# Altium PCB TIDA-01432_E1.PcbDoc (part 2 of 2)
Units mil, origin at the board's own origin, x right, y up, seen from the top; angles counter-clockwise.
Board outline 1228.35 x 2074.8 mil, 4 copper layers (Top Layer, Signal Layer 1, Signal Layer 2, Bottom Layer), stack 61.6 mil thick; 90 components, 49 nets, 292 pads, 293 vias.
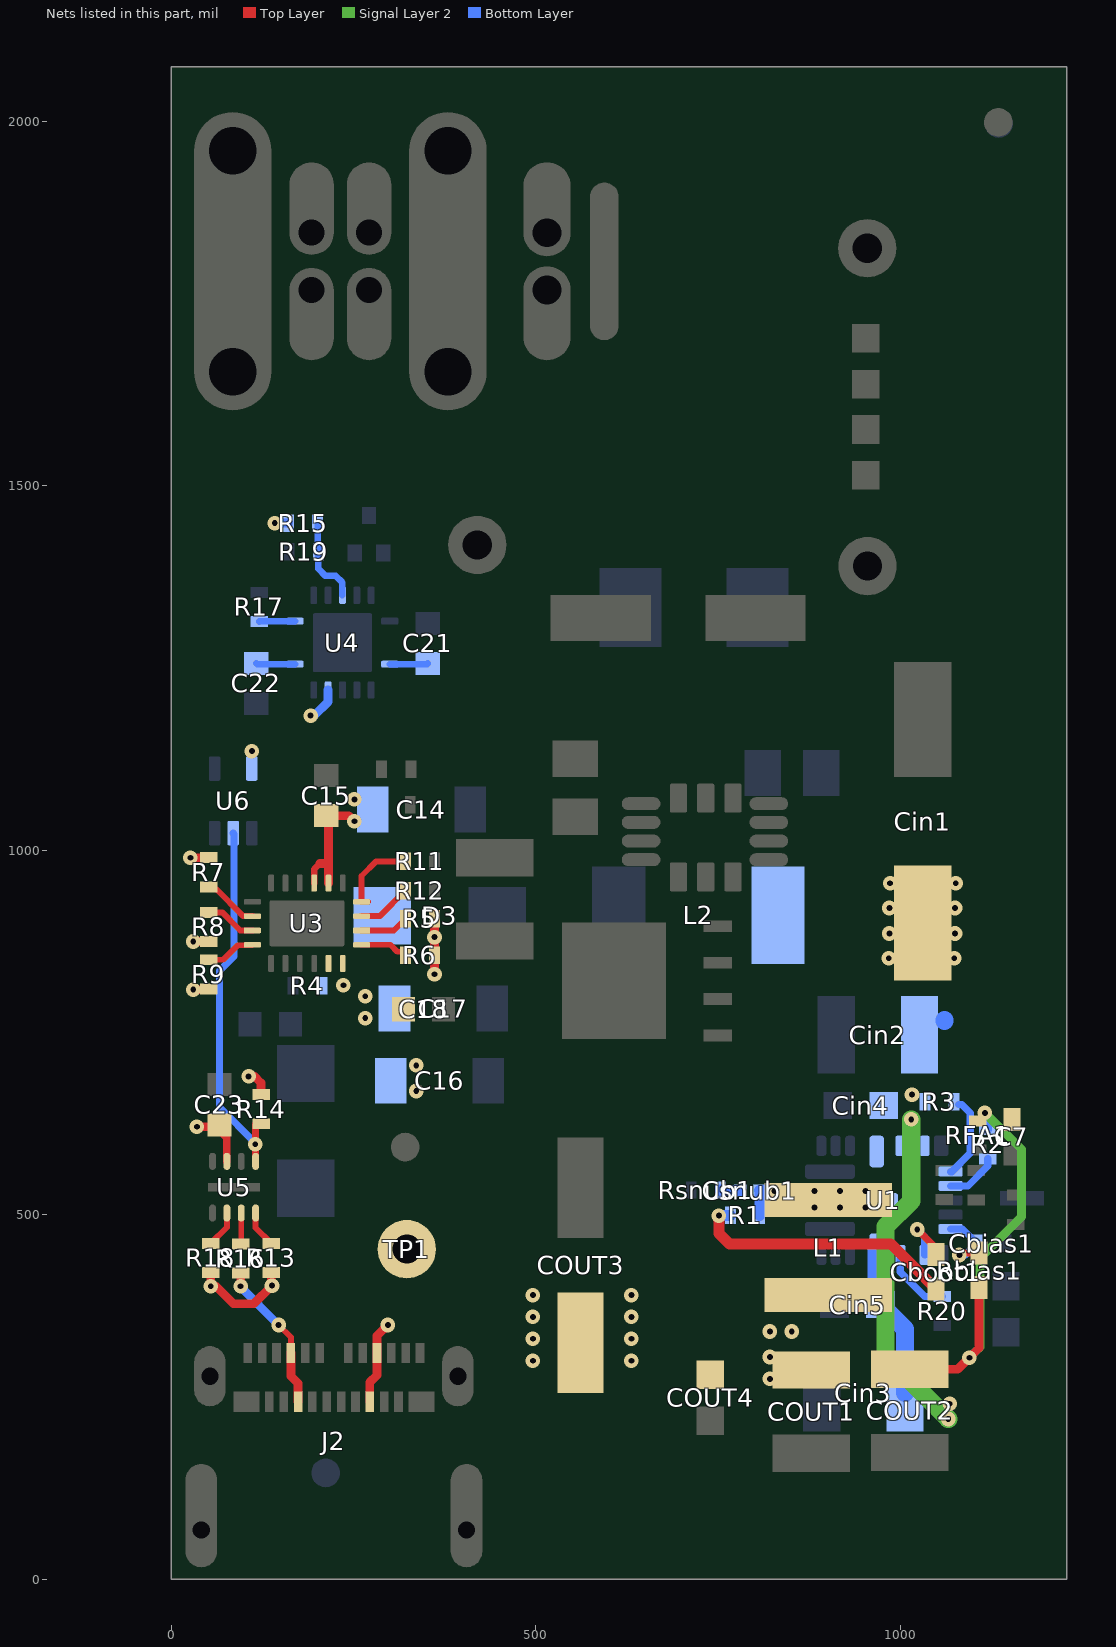
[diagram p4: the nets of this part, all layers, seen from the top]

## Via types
v1: diameter 20, hole 8, Top Layer to Bottom Layer, tented both sides, 274 vias
v2: diameter 19.68, hole 7.87, Top Layer to Bottom Layer, 12 vias
v3: diameter 16, hole 8, Top Layer to Bottom Layer, tented both sides, 7 vias

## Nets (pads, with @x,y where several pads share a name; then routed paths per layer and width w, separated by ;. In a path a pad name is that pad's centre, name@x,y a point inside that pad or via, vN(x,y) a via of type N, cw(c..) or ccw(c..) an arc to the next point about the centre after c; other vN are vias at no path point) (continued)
NetC21_1: C21.1 U4.8 | length 52.4
  Bottom Layer w9: U4.8@299.99,1255.47 351.06,1255.47 C21.1@352.03,1256.44
NetC22_1: C22.1 U4.14 | length 53.5
  Bottom Layer w9: C22.1@117.03,1256.56 118.12,1255.47 U4.14@170.07,1255.47
NetCbias1_2: Cbias1.2 Rbias1.1 U1.22 | length 103
  Top Layer w10: v1(1081.35,445) 1083.97,447.62 Rbias1.1@1108.35,447.62
  Bottom Layer w10: U1.22@1069.18,480.63 1085.72,480.63 Cbias1.2@1105.35,461 1089.35,445 v1(1081.35,445)
NetCboot1_1: Cboot1.1 R1.2 | length 369.8
  Top Layer w15: v1(751.5,499) 751.5,474.5 766,460 987.52,460 Cboot1.1@1049.15,398.38
  Bottom Layer w15: v1(751.5,499) 751.85,499.35 R1.2@767.5,499.35
NetCboot1_2: Cboot1.2 U1.2 | length 84
  Top Layer w10: v1(1023.5,480) 1049.15,454.36 Cboot1.2@1049.15,445.62
  Bottom Layer w10: v1(1023.5,480) 1033.75,469.76 U1.2@1033.75,445.2
NetCsnub1_1: Csnub1.1 Rsnub1.2 | length 27.7
  Bottom Layer w15: Rsnub1.2@753.5,534.15 754,533.65 Csnub1.1@781.01,533.65
NetR2_2: R2.2 U1.19 | length 72.4
  Bottom Layer w10: U1.19@1069.18,539.69 1093.03,539.69 1120.35,567 R2.2@1120.35,576.96
NetR3_1: R3.1 U1.18 | length 113.6
  Bottom Layer w10: U1.18@1069.18,559.37 1070.72,559.37 1096.35,585 1096.35,639.65 1084.65,651.35 R3.1@1080,651.35
NetR5_2: R5.2 U3.18 | length 66.8
  Top Layer w8: U3.18@261.15,890.16 305.5,890.16 R5.2@321.35,906
NetR6_2: R6.2 U3.17 | length 64.1
  Top Layer w8: U3.17@261.15,870.47 300.87,870.47 310.35,861 R6.2@321.35,861
NetR7_2: R7.2 U3.8 | length 65.2
  Top Layer w8: R7.2@61.78,947 98.93,909.84 U3.8@111.54,909.84
NetR8_2: R8.2 U3.9 | length 65.5
  Top Layer w8: R8.2@56.35,915 70.06,915 94.91,890.16 U3.9@111.54,890.16
NetR9_2: R9.2 U3.10 | length 68.7
  Top Layer w8: R9.2@51.35,850 71.35,850 91.35,870 111.07,870 U3.10@111.54,870.47
NetR11_2: R11.2 U3.20 | length 113
  Top Layer w8: U3.20@270.3,929.53 U3.20@261.15,929.53 261.15,964.8 281.35,985 R11.2@321.35,985
NetR12_2: R12.2 U3.19 | length 74.8
  Top Layer w8: U3.19@261.15,909.84 286.19,909.84 R12.2@321.35,945
NetR13_1: R13.1 U5.4 | length 50.5
  Top Layer w8: U5.4@115.87,502.57 115.87,482.47 R13.1@137.35,461
NetR14_1: R14.1 U5.5 U6.2 | length 506.8
  Top Layer w10: U5.5@115.87,573.43 R14.1@115.87,623.47 ; R14.1@123.35,625 R14.1@124.87,623.47
  Bottom Layer w10: U6.2@85.15,1023.71 86.35,1022.51 86.35,855 66.35,835 66.35,647.98 v1@115.87,598.45
  other v1: 115.4,596.91
NetR15_1: R15.1 R19.2 U4.4 | length 123.6
  Bottom Layer w9: R15.1@201.08,1449.04 201.08,1417.96 204.71,1414.32 202,1411.61 202,1386.39 211.76,1376.63 225.76,1376.63 235.03,1367.36 U4.4@235.03,1349.96
NetR16_2: R16.2 U5.3 | length 42.9
  Top Layer w8: R16.2@95.35,460 96.19,460.84 U5.3@96.19,502.57
NetR17_2: R17.2 U4.1 | length 49.3
  Bottom Layer w9: R17.2@121.03,1314 121.56,1314.53 U4.1@170.07,1314.53
NetR18_1: R18.1 U5.2 | length 50.7
  Top Layer w8: R18.1@54.35,461 76.5,483.16 U5.2@76.5,502.57
NetR20_1: R20.1 U1.3 | length 95.2
  Bottom Layer w10: U1.3@1000.28,445.2 1000.28,421.72 1034,388 R20.1@1058,388
P5V: C7.1 C14.1 C15.1 C23.1 COUT1.2 COUT2.2 COUT3.1 COUT4.1 L1.2 R2.1 R5.1 R6.1 R7.1 R8.1 R9.1 R13.2 R14.2 R15.2 R18.2 Rbias1.2 RFA1.2 TP1.1 U3.2 U3.3 U4.12 U5.7 U6.5 | length 1266.3
  Top Layer w9: U3.3@196.19,955.12 196.19,974.42 203.77,982 ; C15.1@212.59,1047.7 C15.1@215.87,1044.42
  Top Layer w10: C23.1@59.35,622.44 76.35,605.44 ; C23.1@76.35,611.44 76.35,605.44 ; U5.7@76.5,573.43 76.35,573.59 76.35,605.44
  Top Layer w12: v1(26.35,990) R7.1@51.35,990 ; v1(30.35,809) 50.35,809 R9.1@51.35,810 ; v1(30.35,875) R8.1@51.35,875 ; v1(35.35,621) 54.91,621 C23.1@56.35,622.44 ; R18.2@54.35,421 v1(54.35,402) 61.58,402 85.46,378.13 113.47,378.13 v1(138.35,403) 137.35,404 R13.2@137.35,421 ; C23.1@59.35,622.44 C23.1@56.35,622.44 ; C23.1@64.35,614.44 C23.1@56.35,622.44 ; v1(106.35,690) 114.35,690 123.35,681 R14.2@123.35,665 ; 203.77,982 215.87,982 ; C15.1@212.59,1047.7 243.64,1047.7 v1(251.35,1040) ; U3.2@215.87,955.12 215.87,982 ; C15.1@215.87,1044.42 215.87,982 ; v1(361.35,830) R6.1@361.35,856 R5.1@361.35,906 ; COUT2.2@1013,288.09 1079.09,288.09 1108.35,317.35 Rbias1.2@1108.35,400.38
  Signal Layer 2 w12: v1(1095,304) 1109.53,318.53 1109.53,440.53 1166.5,497.5 1166.5,589.85 v1(1116.35,640)
  Bottom Layer w12: v1(142.03,1449) 142.08,1449.04 R15.2@161.08,1449.04 ; v1(191.35,1185) 196.35,1185 215.35,1204 U4.12@215.35,1220.04 ; v1(1116.35,640) 1120.35,636 R2.1@1120.35,616.96
  other v1: 821.35,275 496.35,300 631.35,300 821.35,305 496.35,330 631.35,330 821.35,340 851.35,340 496.35,360 631.35,360 496.35,390 631.35,390 361.35,881 251.35,1070 110.74,1136.29
"SW NODE": Csnub1.2 L1.1 R1.1 U1.9 | length 51.5
  Bottom Layer w15: R1.1@807.5,499.35 807.5,533.14 Csnub1.2@806.99,533.65 v3@824,533.65
  other v3: 882.65,510 917.35,510 952.65,510 827.65,533 882.65,533 917.65,533 952.65,533
VBUS: C16.1 C17.1 C18.1 D3.2 J2.A4 J2.A9 J2.B4 J2.B9 R4.2 R16.1 U3.15 U3.16 | length 336.5
  Top Layer w8: v1(147.35,349) 164.29,332.06 J2.A4@164.29,310.6
  Top Layer w12: v1(95.35,402) R16.1@95.35,420 ; 164.29,290.98 164.29,279.06 ; J2.A4@164.29,310.6 164.29,279.06 ; J2.B9@174.13,243.67 174.13,269.21 164.29,279.06 ; J2.B4@272.56,243.67 272.56,270.21 282.35,280 282.35,288 282.4,288.06 J2.A9@282.4,310.6 282.4,334.06 v1(297.35,349)
  Bottom Layer w12: v1(95.35,402) 95.35,401 v1(147.35,349)
  other v1: 336.35,670 336.35,705 266.35,770 266.35,800 236.35,815
VIN: Cin1.1 Cin2.1 Cin3.1 Cin4.1 Cin5.1 L2.2 R3.2 U1.4 U1.14 U1.15 U1.16 | length 662.2
  Signal Layer 2 w25: v1(1015.35,631) 1015.35,519.35 980,484 980,306.15 v1(1066.15,220)
  Bottom Layer w25: U1.4@967.8,453.07 967.8,402.34 Cin5.1@978.14,392 ; Cin5.1@973.14,377 1006.73,343.41 Cin3.1@1006.73,256 ; 1060.85,766.35 1060.85,767
  other v1: 1068,241 1016.35,665 984.35,852 1074.35,852 985.35,886 1075.35,886 985.35,921 1075.35,921 986.35,955 1076.35,955
pads on no net: FID1.1 FID2.1 FID3.1 FID4.1 J1.2 J1.4 J1.@192.72,1735.78 J1.@271.46,1880.47 J2.A2 J2.A3 J2.A8 J2.A10 J2.A11 J2.B2 J2.B3 J2.B8 J2.B10 J2.B11 J2.S1 J2.S2 J2.S3 J2.S4 LBL1.0 U1.4A U1.4B U1.8A U1.8B U1.9A U1.9B U1.9C U1.9D U1.10A U1.10B U1.14A U1.14B U3.21@159.77,900 U3.21@212.92,900 U4.2 U4.3 U4.11 U4.13 U4.15@212.98,1262.95 U4.15@212.98,1307.04 U4.15@257.08,1262.95 U4.15@257.08,1307.04 U6.1 U7.3 U7.5

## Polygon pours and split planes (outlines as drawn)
GND on Signal Layer 1 "SIGNAL_LAYER_1_GND_P010" (solid, remove dead copper, pour order 10): 16.35,2060 1218.5,2060 1218.5,-62.16 1221.35,-65 6.35,-65 6.35,2056.72 9.63,2060 16.35,2060
VIN on Signal Layer 2 "SIGNAL_LAYER_2_VIN_P016" (solid, remove dead copper, pour order 16): 1085,970 961.35,970 961.35,195 1085,195
VBUS on Signal Layer 2 "SIGNAL_LAYER_2_VBUS_P018" (solid, remove dead copper, pour order 18): 311.35,300 176.35,300 141.35,335 141.35,675 161.35,695 251.35,785 356.35,785 356.35,585 241.35,470 241.35,410 241.35,400 261.35,380 266.35,375 311.35,375 311.35,295
P5V on Signal Layer 2 "SIGNAL_LAYER_2_P5V_P022" (solid, remove dead copper, pour order 22): 11.35,2064.8 1218.31,2064.8 1218.5,2065 1221.35,2062.16 1221.35,-65 11.35,-65 11.35,2064.8
GND on Top Layer "TOP_LAYER_GND_P036" (solid, remove dead copper, pour order 36): 20,2050 1210,2050 1210,20 11.19,20 11.19,2050
"INPUT POWER" on Top Layer "TOP_LAYER_INPUT_POWER_P028" (solid, remove dead copper, pour order 28): 550,1773 549,1774 481,1774 481,1503 485,1499 489,1495 825,1495 903,1495 905,1497 905,1673 555,1673 550,1678 550,1777
GND on Bottom Layer "BOTTOM_LAYER_GND_P042" (solid, remove dead copper, pour order 42): 20,2050 1210,2050 1210,20 11.19,20 11.19,2050 20,2050
"INPUT POWER" on Bottom Layer "BOTTOM_LAYER_INPUT_POWER_P040" (solid, remove dead copper, pour order 40): 470,1800 610,1800 630,1800 750,1680 1010,1680 1040,1650 1040,1250 950,1250 920,1220 740,1220 740,1390 660,1470 630,1500 470,1500 470,1800
"INPUT POWER" on Bottom Layer "BOTTOM_LAYER_INPUT_POWER_P038" (solid, remove dead copper, pour order 38): 470,1800 580,1800 580,1690 680,1710 590,1680 1000,1680 1010,1680 1040,1650 1040,1250 765.27,1250 760,1244.73 756.35,1248.39 756.35,1421.9 748.1,1421.9 610,1560 470,1560

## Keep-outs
Keep-Out Layer:
  lines w15: 1165.35,-7.5 1228.35,-7.5 ; 1197,-9.84 638.8,-8.68 -0.39,-7.5 ; -7.89,0 ccw(c-0.39,0) -0.39,-7.5 ; -7.89,0 ccw(c-0.39,0) -0.39,-7.5 ; -7.89,0 -7.89,2074.8 ; -7.89,2074.8 cw(c-0.39,2074.8) -0.39,2082.3 ; -7.89,2074.8 cw(c-0.39,2074.8) -0.39,2082.3 ; -7.5,0 ccw(c0,0) -1.47,-7.36 ; -7.5,0 ccw(c0,0) -1.47,-7.36 ; -7.5,0 -7.5,2074.8 ; -7.5,2074.8 cw(c0,2074.8) 0,2082.3 ; -7.5,2074.8 cw(c0,2074.8) 0,2082.3 ; -1.47,-7.36 ccw(c0,0) 0,-7.5 ; -1.47,-7.36 ccw(c0,0) 0,-7.5 ; -0.39,2082.3 1228.35,2082.3 ; 0,-7.5 1228.35,-7.5 ; 0,2082.3 1228.35,2082.3 ; 1228.35,-7.5 ccw(c1228.35,0) 1235.85,0 ; 1228.35,-7.5 ccw(c1228.35,0) 1235.85,0 ; 1228.35,-7.5 ccw(c1228.35,0) 1235.85,0 ; 1228.35,-7.5 ccw(c1228.35,0) 1235.85,0 ; 1228.35,2082.3 cw(c1228.35,2074.8) 1235.85,2074.8 ; 1228.35,2082.3 cw(c1228.35,2074.8) 1235.85,2074.8 ; 1228.35,2082.3 cw(c1228.35,2074.8) 1235.85,2074.8 ; 1228.35,2082.3 cw(c1228.35,2074.8) 1235.85,2074.8 ; 1235.85,0 1235.85,2074.8 ; 1235.85,0 1235.85,2074.8
  text ".Layer_Name" at 497,-923.49 h40

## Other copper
Top Layer:
  rectangle net "INPUT POWER": 484,1588 547,1710
  rectangle net "INPUT POWER": 480,1460 900,1680
  rectangle net CSPORT: 1129,546 1161,590
  rectangle net "INPUT POWER": 735,1325 1020,1501.97
  rectangle net P5V: 215.87,970 225.35,1044.42
  rectangle net VBUS: 290.35,645 343.35,824
  rectangle net CATHODE: 536.35,920 706.35,995
  rectangle net GND: 690.35,88 1080.35,173
  rectangle net P5V: 1100.35,615 1170.35,655
  rectangle net GND: 351.35,960 496.35,1080
  rectangle net CATHODE: 391.35,820 566.35,900
  rectangle net VBUS: 211.35,755 236.35,850
  rectangle net VBUS: 211.35,755 331.35,825
  rectangle net GND: 356.35,650 461.35,800
  rectangle net GND: 481.35,470 646.35,620
  rectangle net "INPUT POWER": 796.35,1060 936.35,1160
  rectangle net "INPUT POWER": 906.35,1015 936.35,1060
  rectangle net VIN: 961.35,820 1106.35,995
  rectangle net GND: 691.35,125 1031.35,235
  rectangle net GND: 521.35,1240 676.35,1430
  rectangle net "INPUT POWER": 736.35,1230 891.35,1430
  rectangle net GND: 1071.35,110 1195.47,195
  rectangle net GND: 1116.35,680 1201.35,1180
  rectangle net GND: 831.35,695 1156.35,800
  rectangle net GND: 426.35,175 766.35,235
  rectangle net "INPUT POWER": 796.35,1145 936.35,1345
  rectangle net P5V: 191.93,1035 261.35,1075
  rectangle net GND: 191.93,1095 261.35,1135
  rectangle net GND: 135.35,836 145.01,878.35
  rectangle net P5V: 480.79,270 995.61,397.8
  rectangle net "INPUT POWER": 734,1483 1019,1536
  pour cut-out: 999,491.5 997.2,489.7 754.3,489.7 777,467 999,467 999,489.5 999.5,490
  pour cut-out: 784,424.3 805.5,441.5 982.5,441.5 982.5,422.5 979,419 784,419
  text ".Layer_Name" at 497,-923.49 h70
Signal Layer 1:
  text ".Layer_Name" at 472,-921.49 h70
Signal Layer 2:
  rectangle net VIN: 1044,206 1080,253
  rectangle net VBUS: 215,730 295,828.98
  rectangle net P5V: 465.19,482.2 477.51,497.8
  text ".Layer_Name" at 451,-921.49 h70
Bottom Layer:
  rectangle net GND: 86.35,725.26 125.98,800
  rectangle net VIN: 957.65,580 1037.65,670
  rectangle net VIN: 957.65,668.91 1037.65,815.19
  rectangle net VIN: 776.35,845 1091.35,980
  rectangle net VIN: 956.35,735 1091.35,950
  rectangle net "INPUT POWER": 756.35,1235 851.35,1421.9
  rectangle net VBUS: 256.35,650 331.35,950
  rectangle net VBUS: 201.35,755 281.35,826.42
  rectangle net VBUS: 291.35,650 346.35,723.37
  rectangle net CATHODE: 571.35,840 681.35,980
  rectangle net VIN: 956.35,213.3 1031.35,363.3
  rectangle net VIN: 1016.58,205 1071.72,250
  rectangle net P5V: 811.35,265 851.35,350
  rectangle net VIN: 956.35,200 1031.35,213.3
  text ".Layer_Name" at 497,-923.49 h60

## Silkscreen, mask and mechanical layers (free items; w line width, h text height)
Top Overlay:
  circle w10: c819,956 r7.81
  circle w10: c770,1128 r9.34
  region: 1084,33 1084,110 901,110 901,33
  lines w3.94: 341.35,1010 434.35,1103 434.35,1122
  lines w6: 645,1080.95 645,1113 ; 723,1104 723,1130
  text "GND" at 910.27,1901.63 h40
  text "GND" at 390.27,1321.66 h40
  text "INPUT POWER" at 906,1291 h40
  text "5V" at 304.27,518.66 h40
  text "TIDA-01432-" at 460,62 h40
  text ".Layer_Name" at 497,-923.49 h40
Bottom Overlay:
  text ".Layer_Name" at 497,-923.49 h40
Top Paste:
  text ".Layer_Name" at 497,-923.49 h40
Bottom Paste:
  text ".Layer_Name" at 497,-923.49 h40
Top Solder:
  text ".Layer_Name" at 497,-923.49 h40
Bottom Solder:
  text ".Layer_Name" at 497,-923.49 h40
Drill Guide:
  text ".Layer_Name" at 497,-923.49 h40
M1 Board Outline:
  the board outline again, w3.94
  text ".Layer_Name" at 497,-923.49 h60
M2 Board Dimensions:
  rectangle: 45,-465 420,-340
  rectangle: -80,-340 45,-215
  lines w7: -80,-340 920,-340 ; -80,-215 -80,-465 920,-465 920,-215 ; 45,-465 45,-215 ; 170,-465 170,-215 ; 420,-465 420,-215 ; 670,-465 670,-215
  text ".Layer_Name" at 497,-923.49 h60
M3 3D STEP Top:
  text ".Layer_Name" at 497,-923.49 h40
M4 3D STEP Bottom:
  text ".Layer_Name" at 497,-923.49 h40
M5 Assembly Top:
  lines w10: -372,-995.17 6228,-995.17 ; -372,-791.83 6230,-791.83 ; -372,-588.5 -372,-1198.5 3633,-1198.5 6230,-1198.5 6230,-588.5 -371.5,-588.5 -371.5,-1198.5 1204,-1198.5 ; 2093,-1198.5 2093,-588.5 ; 3360,-791.83 3360,-588.5 ; 4200,-791.83 4200,-588.5 ; 4822,-1205 4822,-1002.17
  text "COMPONENTS MARKED 'DNP' SHOULD NOT BE POPULATED." at 1073.5,-383.5 h60
  text "ASSEMBLY VARIANT:" at 1073,-499 h60
  text ".VariantName" at 2109,-499 h60
  text "PCB VIEWED FROM TOP SIDE" at -308.5,-720.67 h60
  text "BOARD #:" at 2168,-720.67 h40
  text ".PRJ_Number" at 2713.5,-720.67 h40
  text "REV:" at 3558,-720.67 h40
  text ".PCB_Rev" at 3849.5,-720.67 h40
  text "SVN REV:" at 4396,-720.67 h40
  text ".VersionControl_RevNumber" at 4902,-720.67 h40
  text "TID #:" at 2168,-924 h40
  text ".TID" at 2713.5,-924 h40
  text ".Layer_Name" at 492.47,-930.49 h70
  text "PLOT NAME =" at -308.5,-1129.34 h60
  text ".plot_File_Name" at 497,-1129.34 h40
  text "GENERATED    :" at 2170,-1129.34 h40
  text ".Print_Date" at 3039.5,-1129.34 h40
  text ".Print_Time" at 3768.5,-1129.34 h40
  text "TEXAS INSTRUMENTS" at 5033,-1129.34 h40
M6 Assembly Bottom:
  lines w10: -372.5,-792.33 6229.5,-792.33 ; -370.5,-995.67 6229.5,-995.67 ; 1035.5,-1205.5 1035.5,-1002.67 ; 1657.5,-792.33 1657.5,-589 ; 2497.5,-792.33 2497.5,-589 ; 3764.5,-1199 3764.5,-589 ; 4653.5,-1199 6229,-1199 6229,-589 -372.5,-589 -372.5,-1199 2224.5,-1199 6229.5,-1199 6229.5,-589
  text "COMPONENTS MARKED 'DNP' SHOULD NOT BE POPULATED." at 6022,-383 h40
  text ".VariantName" at 4978,-499 h40
  text "ASSEMBLY VARIANT:" at 6017,-499 h40
  text ".VersionControl_RevNumber" at 955.5,-721.17 h40
  text "SVN REV:" at 1461.5,-721.17 h40
  text ".PCB_Rev" at 2008,-721.17 h40
  text "REV:" at 2299.5,-721.17 h40
  text ".PRJ_Number" at 3144,-721.17 h40
  text "BOARD #:" at 3689.5,-721.17 h40
  text "PCB VIEWED FROM BOTTOM SIDE" at 6166,-721.17 h40
  text ".TID" at 3144,-924.5 h40
  text "TID #:" at 3689.5,-924.5 h40
  text "TEXAS INSTRUMENTS" at 824.5,-1129.84 h40
  text ".Print_Time" at 2089,-1129.84 h40
  text ".Print_Date" at 2818,-1129.84 h40
  text "GENERATED    :" at 3687.5,-1129.84 h40
  text ".plot_File_Name" at 5360.5,-1129.84 h40
  text "PLOT NAME =" at 6166,-1129.84 h40
M9 Title Sheet:
  drawing of 57 lines, arcs and shapes, not listed
  text "1" at 659.84,7971.5 h40
  text "2" at 3155.5,7971.5 h40
  text "3" at 5644.84,7971.5 h40
  text "4" at 8151.51,7971.5 h40
  text "5" at 10650.5,7971.5 h40
  text "6" at 13155.5,7971.5 h40
  text "A" at -496.5,6828.5 h70
  text "A" at 14303.5,6828.5 h70
  text "B" at -496.5,4448.5 h70
  text "B" at 14303.5,4448.5 h70
  text "C" at -496.5,2073.5 h70
  text "C" at 14303.5,2073.5 h70
  text "PROJECT TITLE:" at 11263.5,212.5 h40
  text ".PRJ_Title" at 11313.5,79.17 h70
  text "DESIGNED FOR:" at 11263.5,-88.5 h40
  text ".PRJ_Customer" at 11313.5,-228.5 h70
  text "D" at -496.5,-296.5 h70
  text "D" at 14303.5,-296.5 h70
  text "FILE NAME:" at 11263.5,-388.5 h40
  text ".PCB_File_Name_No_Path" at 11313.5,-508.5 h70
  text "Texas Instruments (TI) and/or its licensors do not warrant the accuracy or completeness of this specification" at 6302,-677.34 h45
  text "ENGINEER:" at 11263.5,-678.5 h40
  text "LAYOUT BY:" at 12768.5,-678.5 h40
  text "or any information contained therein. TI and/or its licensors do not warrant that this design will meet" at 6257.01,-790 h45
  text ".PRJ_Engineer" at 11313.5,-833.49 h70
  text ".PCB_Layout" at 12819,-833.49 h70
  text "the specifications, will be suitable for your application or fit for any particular purpose, or will operate in" at 6257.01,-902.67 h45
  text ".Layer_Name" at 497,-923.49 h40
  text "ALTIUM DESIGNER VERSION:" at 12768.5,-988.5 h40
  text "an implementation. TI and/or its licensors do not warrant that the design is production worthy. You should" at 6257.01,-1015.33 h45
  text ".print_Scale" at 11313.5,-1121.83 h70
  text ".Application_BuildNumber" at 12819,-1121.83 h70
  text "completely validate and test your design implementation to confirm the system functionality for your application." at 6302,-1128 h45
  text "1" at 659.84,-1328.5 h40
  text "2" at 3155.5,-1328.5 h40
  text "3" at 5644.84,-1328.5 h40
  text "4" at 8151.51,-1328.5 h40
  text "5" at 10650.5,-1328.5 h40
  text "6" at 13155.5,-1328.5 h40
M10 Fab Notes:
  drawing of 173 lines, arcs and shapes, not listed
  text "DESIGN INFORMATION" at 12298.02,6136 h60
  text "MIN. TRACK WIDTH:" at 11653.46,5956 h61
  text "8" at 12749.7,5956 h60
  text "MIL" at 12904.46,5956 h60
  text "8" at 12749.7,5834 h60
  text "MIN. CLEARANCE:" at 11653.46,5824 h61
  text "MIL" at 12904.46,5824 h60
  text "MIN. VIA PAD SIZE:" at 11653.46,5692 h60
  text "16" at 12719.71,5692 h60
  text "MIL" at 12904.46,5692 h60
  text "0.05mm (2MIL)" at 12348.46,5550.29 h60
  text "MINIMUM ANNULAR RING" at 11324.23,5546 h60
  text "EXTERNAL" at 13056.46,5546 h60
  text "PER" at 11524.23,5428 h60
  text "IPC-D-275 CLASS 2 LEVEL C" at 11744.23,5428 h60
  text "MIL, HOLES" at 13232.46,5315.71 h60
  text "+/-" at 12840,5315 h60
  text "+/-" at 13694,5315 h60
  text "REGISTRATION TOLERANCES:" at 11324.23,5310 h60
  text "METAL" at 12524,5310 h60
  text "5" at 13100.2,5310 h60
  text "3" at 13933.2,5310 h60
  text "MIL" at 14049.46,5310 h60
  text "+/-" at 13694,5197 h60
  text "HOLE SIZE TOLERANCE (UNLESS OTHERWISE SPECIFIED):" at 11324.23,5192 h60
  text "3" at 13933.2,5192 h60
  text "MIL" at 14049.46,5192 h60
  text "MATERIAL:" at 11249.46,4982.54 h60
  text "FR-4 High Tg" at 12235.9,4842.21 h60
  text "FR-408" at 11670.46,4833.64 h60
  text "OTHER" at 13158.46,4833.64 h60
  text "X" at 12081,4830 h60
  text "62 MIL (1.6mm) +/-10%" at 11990.56,4670.92 h60
  text "THICKNESS:" at 11324.23,4666.64 h60
  text "X" at 11862.4,4666.64 h60
  text "OTHER" at 13275.46,4666.64 h60
  text "TOLERANCE:" at 11324.23,4508.64 h60
  text "X" at 12163.53,4508.64 h60
  text "ANSI IPC-6012 TYPE 3 CLASS 2" at 12350.48,4508.64 h60
  text "OTHER +/-" at 12350.46,4352.64 h60
  text "BOW & TWIST:" at 11324.23,4195.64 h60
  text "X" at 12163.53,4195.64 h60
  text "ANSI IPC-6012 TYPE 3 CLASS 2" at 12350.48,4195.64 h60
  text "OTHER +/-" at 12350.46,4037.13 h60
  text "DRILLING:" at 11249.46,3898.64 h60
  text "REFERENCE:" at 11324.23,3781.64 h60
  text "X" at 11972.46,3781.64 h60
  text "AS SHOWN" at 12159.46,3781.64 h60
  text "X" at 12873.46,3781.64 h60
  text "NC_DRILL FILES" at 13010.46,3781.64 h60
  text "PTH COPPER THICKNESS:" at 11324.23,3623.64 h60
  text "X" at 12454.46,3623.64 h60
  text "20-30 um" at 12591.46,3623.64 h60
  text "OTHER" at 13308.46,3623.64 h60
  text "BOARD FINISH:" at 11249.46,3464.64 h60
  text "SILKSCREEN:" at 11404.68,3346.64 h60
  text "X" at 12353.46,3346.64 h60
  text "TOP" at 12479.46,3346.64 h60
  text "X" at 12863.46,3346.64 h60
  text "BOTTOM" at 12990.46,3346.64 h60
  text "SILKSCREEN COLOR:" at 11404.68,3179.64 h60
  text "X" at 12352.42,3179.64 h60
  text "WHITE" at 12479.46,3179.64 h60
  text "OTHER" at 12990.46,3179.64 h60
  text "X" at 12483.42,3020.44 h60
  text "GREEN" at 12610.46,3020.44 h60
  text "OTHER" at 13228.46,3020.44 h60
  text "SOLDER RESIST COLOR:" at 11404.68,3009.64 h60
  text "X" at 12483.42,2850.44 h60
  text "MATTE" at 12610.46,2850.44 h60
  text "SEMI-GLOSS" at 13228,2849.8 h60
  text "IMMERSION GOLD (ENIG)" at 12310.46,2661.92 h60
  text "ENEPIG" at 13648,2658.64 h60
  text "SURFACE FINISH:" at 11249.46,2657.64 h60
  text "X" at 12123.51,2657.64 h60
  text "IMM. TIN/SILVER OR EQUIV" at 11579,2500.64 h60
  text "OTHER" at 13010.46,2500.64 h60
  text "ARRAY/PANEL:" at 11249.46,2321.64 h60
  text "CUT AND TRIM PER M1 BOARD OUTLINE" at 12310.46,2317.35 h60
  text "N.C. ROUTE" at 12310.46,2165.64 h60
  text "V. SCORE" at 13176.46,2165.64 h60
  text "X" at 12099.46,2155.64 h60
  text "CERTIFICATION:" at 11249.46,2028.64 h60
  text "MATERIALS AND WORKMANSHIP FOR ALL PCBS" at 11974.46,2028.64 h60
  text "TO MEET OR EXCEED THE REQUIREMENTS OF:" at 11974.46,1930.64 h60
  text "X" at 11600.96,1794.13 h60
  text "ANSI IPC-A-600F CLASS ->" at 11739.96,1794.13 h60
  text "X" at 13379.02,1794.13 h60
  text "2" at 13497.96,1794.14 h60
  text "1" at 13182.96,1792.64 h60
  text "3" at 13851.96,1792.64 h60
  text "X" at 12415.02,1634.64 h60
  text "RoHS" at 12551.96,1634.64 h60
  text "OTHER" at 13196.36,1634.64 h60
  text "PER ORDER" at 13593.42,1634.64 h60
  text "ALL BOARDS MUST MEET OR EXCEED UL94-V0 REQUIREMENTS." at 11277,1469 h60
  text "PCB MUST BEAR THE UL94V-0 UL REGISTERED MATERIAL ID NUMBER" at 11277,1349 h60
  text "ADDITIONAL REQUIREMENTS:" at 11249.46,1175.64 h60
  text "MICROSECTION:" at 11324.23,1060.64 h60
  text "YES" at 12229.96,1060.64 h60
  text "REQUIRED" at 13091.46,904.49 h60
  text "BARE BOARD ELEC. TEST:" at 11324.23,901.64 h60
  text "NONE" at 12629.96,901.64 h60
  text "X" at 12964.46,901.64 h60
  text "PER ORDER" at 13683.46,901.64 h60
  text ".Layer_Name" at 497,-923.49 h60
M11 Gerber Information:
  lines w10: -372,-995.17 6228,-995.17 ; -372,-791.83 6230,-791.83 ; -372,-588.5 -372,-1198.5 3633,-1198.5 6230,-1198.5 6230,-588.5 -371.5,-588.5 -371.5,-1198.5 1204,-1198.5 ; 2093,-1198.5 2093,-588.5 ; 3360,-791.83 3360,-588.5 ; 4200,-791.83 4200,-588.5 ; 4822,-1205 4822,-1002.17
  text "ALL ARTWORK VIEWED FROM TOP SIDE" at -308.5,-720.67 h40
  text "BOARD #:" at 2168,-720.67 h40
  text ".PRJ_Number" at 2713.5,-720.67 h40
  text "REV:" at 3558,-720.67 h40
  text ".PCB_Rev" at 3849.5,-720.67 h40
  text "SVN REV:" at 4396,-720.67 h40
  text ".VersionControl_RevNumber" at 4902,-720.67 h40
  text "LAYER NAME =" at -308.5,-923.49 h40
  text "TID #:" at 2168,-924 h40
  text ".TID" at 2713.5,-924 h40
  text "PLOT NAME =" at -308.5,-1129.34 h40
  text ".plot_File_Name" at 497,-1129.34 h40
  text "GENERATED    :" at 2170,-1129.34 h40
  text ".Print_Date" at 3039.5,-1129.34 h40
  text ".Print_Time" at 3768.5,-1129.34 h40
  text "TEXAS INSTRUMENTS" at 5033,-1129.34 h40
M12 Stackup:
  drawing of 295 lines, arcs and shapes, not listed
  text "Layer" at 10124.84,7815 h40
  text "Name" at 10404.79,7815 h40
  text "Material" at 11037.95,7815 h40
  text "Thickness" at 11617.79,7815 h40
  text "Constant" at 12057.68,7815 h40
  text "Board Layer Stack" at 12444.26,7815 h40
  text "1" at 10124.84,7735 h40
  text "Top Overlay" at 10404.79,7735 h40
  text "2" at 10124.84,7655 h40
  text "Top Solder" at 10404.79,7655 h40
  text "Solder Resist" at 11037.95,7655 h40
  text "0.40mil" at 11617.79,7655 h40
  text "3.5" at 12057.68,7655 h40
  text "3" at 10124.84,7575 h40
  text "Top Layer" at 10404.79,7575 h40
  text "Copper" at 11037.95,7575 h40
  text "1.40mil" at 11617.79,7575 h40
  text "4" at 10124.84,7495 h40
  text "Dielectric1" at 10404.79,7495 h40
  text "FR-4" at 11037.95,7495 h40
  text "6.00mil" at 11617.79,7495 h40
  text "4.8" at 12057.68,7495 h40
  text "5" at 10124.84,7415 h40
  text "Signal Layer 1" at 10404.79,7415 h40
  text "Copper" at 11037.95,7415 h40
  text "1.40mil" at 11617.79,7415 h40
  text "6" at 10124.84,7335 h40
  text "Dielectric2" at 10404.79,7335 h40
  text "44.00mil" at 11617.79,7335 h40
  text "4.2" at 12057.68,7335 h40
  text "7" at 10124.84,7255 h40
  text "Signal Layer 2" at 10404.79,7255 h40
  text "Copper" at 11037.95,7255 h40
  text "1.40mil" at 11617.79,7255 h40
  text "8" at 10124.84,7175 h40
  text "Dielectric 3" at 10404.79,7175 h40
  text "6.00mil" at 11617.79,7175 h40
  text "4.2" at 12057.68,7175 h40
  text "9" at 10124.84,7095 h40
  text "Bottom Layer" at 10404.79,7095 h40
  text "Copper" at 11037.95,7095 h40
  text "1.40mil" at 11617.79,7095 h40
  text "10" at 10124.84,7015 h40
  text "Bottom Solder" at 10404.79,7015 h40
  text "Solder Resist" at 11037.95,7015 h40
  text "0.40mil" at 11617.79,7015 h40
  text "3.5" at 12057.68,7015 h40
  text "11" at 10124.84,6935 h40
  text "Bottom Overlay" at 10404.79,6935 h40
  text ".Layer_Name" at 497,-923.49 h40
M13 Component Bodies Top:
  text ".Layer_Name" at 497,-923.49 h40
M14 Component Bodies Bottom:
  text ".Layer_Name" at 497,-923.49 h40
M15 Courtyards Top:
  text ".Layer_Name" at 497,-923.49 h40
M16 Courtyards Bottom:
  text ".Layer_Name" at 497,-923.49 h40
Drill Drawing:
  circle w10: c1647.3,2085.18 r16.59
  circle w10: c1647.3,2085.18 r27.66
  lines w10: 1619.64,1186.31 1619.64,1200.14 1633.47,1213.97 1619.64,1227.79 1619.64,1241.62 1633.47,1241.62 1647.3,1227.79 1661.13,1241.62 1674.96,1241.62 1674.96,1227.79 1661.13,1213.97 1674.96,1200.14 1674.96,1186.31 1661.13,1186.31 1647.3,1200.14 1633.47,1186.31 1619.64,1186.31 ; 1619.64,1338.42 1647.3,1310.77 1674.96,1338.42 1647.3,1366.08 1619.64,1338.42 ; 1619.64,1449.05 1633.47,1449.05 1647.3,1435.23 1661.13,1449.05 1674.96,1449.05 1661.13,1462.88 1674.96,1476.71 1661.13,1476.71 1647.3,1490.54 1633.47,1476.71 1619.64,1476.71 1633.47,1462.88 1619.64,1449.05 ; 1619.64,1559.68 1674.96,1559.68 1674.96,1615 1619.64,1615 1619.64,1559.68 ; 1619.64,1739.46 1674.96,1739.46 1647.3,1684.14 1619.64,1739.46 ; 1619.64,1808.6 1647.3,1822.43 1674.96,1808.6 1661.13,1836.26 1674.96,1863.92 1647.3,1850.09 1619.64,1863.92 1633.47,1836.26 1619.64,1808.6 ; 1619.64,1988.38 1674.96,1988.38 1647.3,1933.06 1619.64,1988.38 ; 1630.71,1977.31 1663.89,1977.31 1647.3,1944.12 1630.71,1977.31
  lines w12: 1569.5,1148.97 5364.01,1148.97 ; 1569.5,2144.64 5364.01,2144.64 ; 1907.67,1024.51 1907.67,2269.1 ; 2239.78,1024.51 2239.78,2269.1 ; 2876.79,1024.51 2876.79,2269.1 ; 3136.14,1024.51 3136.14,2269.1 ; 3511.56,1024.51 3511.56,2269.1 ; 4235.41,1024.51 4235.41,2269.1 ; 4764.92,1024.51 4764.92,2269.1 ; 1569.5,1024.51 5364.01,1024.51 5364.01,2269.1 1569.5,2269.1 1569.5,1024.51
  text "Symbol" at 1644.18,2181.98 h72
  text "Quantity" at 1945.01,2181.98 h72
  text "Finished Hole Size" at 2277.12,2181.98 h72
  text "Plated" at 2914.12,2181.98 h72
  text "Hole Type" at 3173.48,2181.98 h72
  text "Drill Layer Pair" at 3548.9,2181.98 h72
  text "Hole Tolerance" at 4272.75,2181.98 h72
  text "Hole Length" at 4802.26,2181.98 h72
  text "12" at 1945.01,2057.52 h60
  text "7.87mil (0.200mm)" at 2277.12,2057.52 h60
  text "PTH" at 2914.12,2057.52 h60
  text "Round" at 3173.48,2057.52 h60
  text "Top Layer - Bottom Layer" at 3548.9,2057.52 h60
  text "-" at 4802.26,2057.52 h60
  text "281" at 1945.01,1933.06 h60
  text "8.00mil (0.203mm)" at 2277.12,1933.06 h60
  text "PTH" at 2914.12,1933.06 h60
  text "Round" at 3173.48,1933.06 h60
  text "Top Layer - Bottom Layer" at 3548.9,1933.06 h60
  text "-" at 4802.26,1933.06 h60
  text "4" at 1945.01,1808.6 h60
  text "35.43mil (0.900mm)" at 2277.12,1808.6 h60
  text "PTH" at 2914.12,1808.6 h60
  text "Round" at 3173.48,1808.6 h60
  text "Top Layer - Bottom Layer" at 3548.9,1808.6 h60
  text "+3.94mil" at 4272.75,1808.6 h60
  text "-" at 4802.26,1808.6 h60
  text "2" at 1945.01,1684.14 h60
  text "39.37mil (1.000mm)" at 2277.12,1684.14 h60
  text "PTH" at 2914.12,1684.14 h60
  text "Round" at 3173.48,1684.14 h60
  text "Top Layer - Bottom Layer" at 3548.9,1684.14 h60
  text "+3.94mil" at 4272.75,1684.14 h60
  text "-" at 4802.26,1684.14 h60
  text "4" at 1945.01,1559.68 h60
  text "40.00mil (1.016mm)" at 2277.12,1559.68 h60
  text "PTH" at 2914.12,1559.68 h60
  text "Round" at 3173.48,1559.68 h60
  text "Top Layer - Bottom Layer" at 3548.9,1559.68 h60
  text "-" at 4802.26,1559.68 h60
  text "4" at 1945.01,1435.23 h60
  text "64.96mil (1.650mm)" at 2277.12,1435.23 h60
  text "PTH" at 2914.12,1435.23 h60
  text "Round" at 3173.48,1435.23 h60
  text "Top Layer - Bottom Layer" at 3548.9,1435.23 h60
  text "+3.94mil" at 4272.75,1435.23 h60
  text "-" at 4802.26,1435.23 h60
  text "2" at 1945.01,1310.77 h60
  text "23.62mil (0.600mm)" at 2277.12,1310.77 h60
  text "PTH" at 2914.12,1310.77 h60
  text "Slot" at 3173.48,1310.77 h60
  text "Top Layer - Bottom Layer" at 3548.9,1310.77 h60
  text "+/-1.97mil" at 4272.75,1310.77 h60
  text "62.99mil (1.600mm)" at 4802.26,1310.77 h60
  text "2" at 1945.01,1186.31 h60
  text "23.62mil (0.600mm)" at 2277.12,1186.31 h60
  text "PTH" at 2914.12,1186.31 h60
  text "Slot" at 3173.48,1186.31 h60
  text "Top Layer - Bottom Layer" at 3548.9,1186.31 h60
  text "+/-1.97mil" at 4272.75,1186.31 h60
  text "82.68mil (2.100mm)" at 4802.26,1186.31 h60
  text "311 Total" at 1945.01,1061.85 h60
  text "Slot definitions :" at 1644.18,974.73 h60
  text "Routed Path Length" at 2094.58,974.73 h60
  text "= Calculated from tool start centre position to tool end centre position." at 2633.79,974.73 h60
  text "Hole Length" at 2094.58,924.95 h60
  text "= Routed Path Length + Tool Size = Slot length as defined in the PCB layout" at 2434.19,924.95 h60
  text ".Layer_Name" at 497,-923.49 h60
M17 Embedded Cavity:
  text ".Layer_Name" at 497,-923.49 h40
M18 Embedded Assembly:
  text ".Layer_Name" at 497,-923.49 h40
M19 Embedded Keepout:
  text ".Layer_Name" at 497,-923.49 h40
Mechanical 20:
  lines w0.05: 557.79,-10 1.35,-10 ; 557.79,9.68 1.35,9.68 -3.57,8.37 -7.18,4.76 -8.5,-0.16 ; 664.64,2.84 1129.2,2.84 ; 1155.05,8.01 1160.82,9.26 1166.7,9.68 ; 1155.88,-12.91 1161.1,-10.74 1166.7,-10 ; 1158.18,-5.08 1161.78,-8.68 1166.7,-10 ; 1158.18,4.76 1161.78,8.37 1166.7,9.68 ; -8.5,-0.16 -7.18,-5.08 ; -8.5,-0.16 -7.18,-5.08 ; -8.5,-0.16 -8.5,2074.65 ; -8.5,2074.65 -7.18,2079.57 ; -8.5,2074.65 -7.18,2069.72 -3.57,2066.12 1.35,2064.8 1229.69,2064.8 1234.61,2066.12 1238.22,2069.72 1239.54,2074.65 ; -8.5,2074.65 -7.18,2079.57 ; -7.18,-5.08 -3.57,-8.68 ; -7.18,-5.08 -3.57,-8.68 ; -7.18,2079.57 -3.57,2083.17 ; -7.18,2079.57 -3.57,2083.17 ; -3.57,-8.68 1.35,-10 ; -3.57,-8.68 1.35,-10 ; -3.57,2083.17 1.35,2084.49 ; -3.57,2083.17 1.35,2084.49 ; 1.35,-10 6.27,-8.68 9.87,-5.08 11.19,-0.16 11.19,2074.65 9.87,2079.57 6.27,2083.17 1.35,2084.49 ; 1.35,2084.49 1229.69,2084.49 ; 1166.7,-10 1229.69,-10 ; 1166.7,-10 1171.63,-8.68 1175.22,-5.08 1176.54,-0.16 1175.22,4.76 1171.62,8.37 1166.7,9.68 ; 1166.7,9.68 1229.69,9.68 1234.61,8.37 1238.22,4.76 1239.54,-0.16 ; 1166.7,9.68 1166.7,9.68 ; 1229.69,-10 1234.61,-8.68 ; 1229.69,-10 1224.77,-8.68 1221.17,-5.08 1219.85,-0.16 1219.85,2074.65 1221.17,2079.57 1224.77,2083.17 1229.69,2084.49 ; 1229.69,-10 1234.61,-8.68 ; 1229.69,2084.49 1234.61,2083.17 ; 1229.69,2084.49 1234.61,2083.17 ; 1234.61,-8.68 1238.22,-5.08 ; 1234.61,-8.68 1238.22,-5.08 ; 1234.61,2083.17 1238.22,2079.57 ; 1234.61,2083.17 1238.22,2079.57 ; 1238.22,-5.08 1239.54,-0.16 ; 1238.22,-5.08 1239.54,-0.16 ; 1238.22,2079.57 1239.54,2074.65 ; 1238.22,2079.57 1239.54,2074.65 ; 1239.54,-0.16 1239.54,2074.65

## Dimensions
-0.39,2074.8 to 1228.35,2074.8 on M2 Board Dimensions
0,0 to 0,2074.8 on M2 Board Dimensions
-80,-465 to 920,-465 on M2 Board Dimensions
